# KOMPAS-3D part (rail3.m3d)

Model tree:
1. X Axis
2. Y Axis
3. Z Axis
4. Origin  (labels: D:\Program Files\ASCON\KOMPAS-3D V10\Sys\GRAPHIC_EN.LYT; Rail 03)
     Wall Thickness 1 = 1; Wall Thickness 2 = 1; Distance 1 = 50; Distance 2 = 10

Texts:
  Rail 03
  Three Point Plane
  Plane at Angle
  Line and Point Plane
  Axis through Two Vertices
  Axis of Feature
  Axis of Conical Surface
  Axis through Edge
  Trim by Surface
  Trim by Sketch
  Feature with No History
  Intersection Axis of Two Planes
  Two Line Plane
  Line and Face Plane
  Bend by line
  Hole in sheet body
  Cut in sheet body
  Point in CM
  Linear Dimension from Line to Point
  Surface Finish Symbol
  Geometric Tolerance Symbol
  Leader #1
  Leader #2
  Leader #3
  Shape Deviations and Datum
  Node point number
  Mark of coordination axis
  Node point designation
  Mark/Reference designation with leader
  Mark/reference designation on line
  Mark/Reference designation without leader
  LR2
